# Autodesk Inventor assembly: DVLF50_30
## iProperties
Created: 2010-03
Part Number: DVLF50_30
Document SubType Name: Assembly
Designer: TB
Mass: 802.733 g
Surface Area: 1529.19 cm^2
Volume: 802.733 cm^3
Density: 1 g/cm^3
Description: KM DVLF 50/30 - 100 mm
Slaglengde: 100.000 mm
Author: TB
